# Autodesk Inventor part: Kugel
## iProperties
Author: Benedict
Created: 2003-07
Part Number: Kugel
Material: Standard
Document SubType Name: Modellieren
Designer: Benedict
Control State: 0
Master: False
Checked Out: True
Checked Out By: Benedict
Checked Out Date: 2003-07-15
PropertySet Name: Design Tracking Control
Shininess: 20.0
Angle Display Precision: 2
Document Length Units: 11269
Document Angle Units: 11283
Document Time Units: 11279
Document Mass Units: 11290
Document Length Units Precision: 3
Document Angle Units Precision: 2
Compacted: False
PropertySet Name: _Private Model Information
Density: 0.0
Volumn: 0.0
Area: 0.0
PropertySet Name: Model Information
